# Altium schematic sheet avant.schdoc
size 297 x 209 mm; Symbol: Drawing-Symbol_A4; @Project Name: Assisant vocal; @Page Count: 1; @Update Date: 2026-03-26; @Create Date: 2026-03-26; @Schematic Name: avant; @Page No: 1; @Page Name: avant; Company: EasyEDA.com; Version: V1.0; Page Size: A4; @Create Time: 09:55:51; @Update Time: 10:05:27; Border: 1; Width: 1170; Height: 825; Region Start: 1; X Region Count: 6; Y Region Count: 4; Blade Width: 10; Title Block Position: 3; @Board Name: avant; Device: Drawing-Symbol_A4
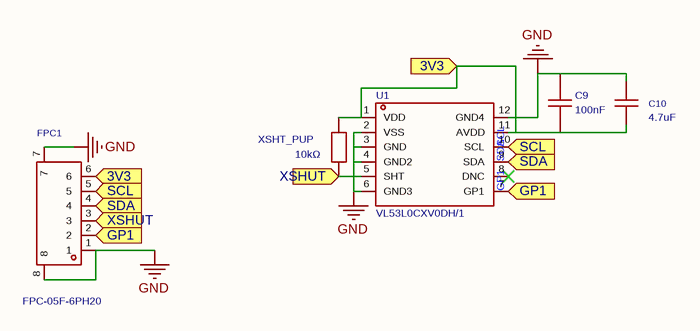
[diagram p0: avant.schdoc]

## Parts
C9  100nF  [C0603]
C10  4.7uF  [C0603]
FPC1  FPC-05F-6PH20  [FPC-SMD_6P-P0.50_XUNPU_FPC-05F-6PH20]
U1  VL53L0CXV0DH/1  [OPTO-SMD_12P_VL53L0CXV0DH-1]
XSHT_PUP  10kΩ  [R0603]

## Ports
3V3 (in), GP1 (in), SCL (in), SDA (in), XSHUT (in)

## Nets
GND: C9.2 C10.2 FPC1.1 FPC1.7 FPC1.8 U1.2(VSS) U1.3(GND) U1.4(GND2) U1.6(GND3) U1.12(GND4)
3V3: C9.1 C10.1 FPC1.6 U1.1(VDD) U1.11(AVDD) XSHT_PUP.2 ; port 3V3
GP1: FPC1.2 U1.7(GP1) ; port GP1
SCL: FPC1.5 U1.10(SCL) ; port SCL
SDA: FPC1.4 U1.9(SDA) ; port SDA
XSHUT: FPC1.3 U1.5(SHT) XSHT_PUP.1 ; port XSHUT

Not connected (* = marked no-connect by the designer): U1 8(DNC)*

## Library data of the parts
C9 = CC0603KRX7R9BB104: Capacitance:100nF Tolerance:±10% Tolerance:±10% Voltage Rating:50V Temperature Coefficient:X7R; Manufacturer: YAGEO(国巨); AddInBom: yes; ModelId: 624118aa3cc7497086c383c2d72e0852; ModelName: C0603_L1.6-W0.8-H0.8; ModelTransform: 62.992,31.496,0,0,0,0,0,0,0; Tolerance: ±10%; Voltage Rating: 50V; Temperature Coefficient: X7R
C10 = CL10A475KP8NNNC: Capacitance:4.7uF Tolerance:±10% Tolerance:±10% Voltage Rating:10V Temperature Coefficient:X5R; Manufacturer: SAMSUNG(三星); AddInBom: yes; ModelId: 624118aa3cc7497086c383c2d72e0852; ModelName: C0603_L1.6-W0.8-H0.8; ModelTransform: 62.992,31.496,0,0,0,0,0,0,0; Tolerance: ±10%; Voltage Rating: 10V; Temperature Coefficient: X5R
FPC1 = FPC-05F-6PH20: Locking Feature:Hinged Lid Contact Type:Surface Mount Number of Contacts:6P Pitch:0.5mm Mounting Type:Bottom Contact FFC, FCB Thickness:0.3mm FFC, FCB Thickness:0.3mm Height Above Board:2mm Contact Material:Phosphor Bronze Contact Plating:Tin Operating Te; Manufacturer: XUNPU(讯普); AddInBom: yes; ModelId: 03841dd804654387977a90b8a5524c4d; ModelTransform: 291.338,220.472,0,0,0,0,-0.001,-45.276,0; Number of Contacts: 6P; Pitch: 0.5mm; FFC, FCB Thickness: 0.3mm; Rated Voltage (Max): 50V; Current Rating (Max): 500mA
U1 = VL53L0CXV0DH/1: Linear Range:200cm Linear Range:200cm; Manufacturer: ST(意法半导体); AddInBom: yes; ModelId: 2e27dd61857247089f19d2c7d77daa5a; ModelTransform: 94.488,173.228,0,90,0,0,0,0,0; Linear Range: 200cm
XSHT_PUP = FRC0603J103 TS: Type:Thick Film Resistor Resistance:10kΩ Tolerance:±5% Tolerance:±5% Power(Watts):100mW Voltage-Supply(Max):75V Temperature Coefficient:±100ppm/℃ Temperature Coefficient:±100ppm/℃ Operating Temperature:-55℃~+155℃ Operating Temperature:-55℃~+155℃; Manufacturer: FOJAN(富捷); AddInBom: yes; ModelId: 112863783b5b41f1b5254f87eedc7932; ModelTransform: 31.8897,63.7794,0,90,0,0,0,0,0; Tolerance: ±5%; Power(Watts): 100mW; Voltage-Supply(Max): 75V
